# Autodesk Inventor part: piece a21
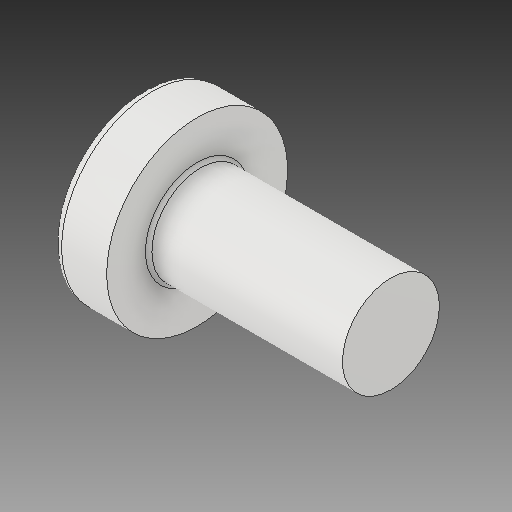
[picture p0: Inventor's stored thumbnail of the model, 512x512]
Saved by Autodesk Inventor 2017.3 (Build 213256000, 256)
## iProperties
Created: 1999-08
Part Number: piece a21
Material: solidworks materials|Alliage 7079|22
Document SubType Name: Modeling
Designer: ficho
Density: 2.7 g/cm^3
Appearance: 255,255,255
Author: ficho
Sending System: SolidWorks 2009
Last Author: christophe
Last Saved: 2011-01-17
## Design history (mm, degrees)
feature "RecessCore"
node "Solide1"
